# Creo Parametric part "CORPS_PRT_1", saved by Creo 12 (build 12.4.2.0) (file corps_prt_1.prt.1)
Units: Custom; MM, KILOGRAM, SECS

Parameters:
  PTC_WM_ITERATION = "0"
  PTC_WM_VERSION = "-.0"
  PTC_WM_LIFECYCLE_STATE = "In Work"
  PTC_WM_LIFECYCLE = "MO_CADDocument"
  PTC_WM_CREATED_BY = "Maximilian Roepper (Z0017RMS: MO)"
  PTC_WM_CREATED_ON = "18-Sep-26 11:36:42 AM"
  PTC_WM_MODIFIED_BY = "Maximilian Roepper (Z0017RMS: MO)"
  PTC_WM_MODIFIED_ON = "18-Sep-26 11:36:46 AM"
  PDMLINKNUMBER = "PDM000071455047"
  PTC_WM_NAME = "corps_prt_1.prt"
  PTC_WM_NUMBER = "PDM000071455047"

Other parameters: WEIGHT, WEIGHT_FACTOR, WEIGHT_ADD, _MASS_TEMP, _DIFF_TEMP, MC_ERRORS, SUPPLIER

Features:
  1. coordinate system
  2. datum plane "PRT_YZ"
  3. datum plane "PRT_XY"
  4. datum plane "PRT_XZ"
  5. coordinate system
  6. datum axis
  7. datum axis
  8. datum axis
  9. coordinate system
  10. imported feature
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
Other named items: PRT, SIEMENS_MO, DRW_VIEW_ORG, PRT_X, PRT_Y, PRT_Z, CS0, ROUGH_GROB

Layers: 00_STD_CSYS-KSYS, 01_STD_PLANES-EBENEN, 02_STD_AXES-ACHSEN, 03_STD_CSYS-KSYS, 24_IMPORT_FEAT-IMPORT_KE

Surfaces: 8 cylinder, 4 plane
